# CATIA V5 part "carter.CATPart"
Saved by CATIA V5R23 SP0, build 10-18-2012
Part number: carter
Definition: carter
Source: made
Bounding box of the stored display mesh (mm): x -112 to 125, y -159 to 104, z -70 to 70
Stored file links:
  C:\wamp\www\COURS\CONCEPTION GMP1\TITRE 01-CATIA VOLUMIQUE\05--ACTIONNEUR DE VANNE\prof\CORRECTION\Assemblage\carter.CATPart
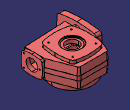
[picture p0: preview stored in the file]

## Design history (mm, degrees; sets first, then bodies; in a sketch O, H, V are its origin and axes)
Body1 "NONE" (main body)
  Solid1 "Manifold Solid #7438": solid without history
  Sketch1 "Esquisse.1" on face of Solid1, origin (125, 0, 0), H (0, 1, 0), V (0, 0, 1)
    projected arc E1 centre (-27.6401, 29.844) radius 10 from (-17.7954, 31.5995) to (-25.4425, 39.5995) ccw from edge [face of Solid1 | face of Solid1]
    projected arc E2 centre (-65, -136) radius 180 from (-25.4425, 39.5995) to (-65, 44) ccw from edge [face of Solid1 | face of Solid1]
    projected arc E3 centre (-65, -136) radius 180 from (-65, 44) to (-104.5575, 39.5995) ccw from edge [face of Solid1 | face of Solid1]
    projected arc E4 centre (-102.3599, 29.844) radius 10 from (-104.5575, 39.5995) to (-112.2046, 31.5995) ccw from edge [face of Solid1 | face of Solid1]
    projected arc E5 centre (65, 0) radius 180 from (-112.2046, 31.5995) to (-112.2046, -31.5995) ccw from edge [face of Solid1 | face of Solid1]
    projected arc E6 centre (-102.3599, -29.844) radius 10 from (-112.2046, -31.5995) to (-104.5575, -39.5995) ccw from edge [face of Solid1 | face of Solid1]
    projected arc E7 centre (-65, 136) radius 180 from (-104.5575, -39.5995) to (-65, -44) ccw from edge [face of Solid1 | face of Solid1]
    projected arc E8 centre (-65, 136) radius 180 from (-65, -44) to (-25.4425, -39.5995) ccw from edge [face of Solid1 | face of Solid1]
    projected arc E9 centre (-27.6401, -29.844) radius 10 from (-25.4425, -39.5995) to (-17.7954, -31.5995) ccw from edge [face of Solid1 | face of Solid1]
    projected arc E10 centre (-195, 0) radius 180 from (-17.7954, -31.5995) to (-17.7954, 31.5995) ccw from edge [face of Solid1 | face of Solid1]
    projected arc E11 centre (-65, 0) radius 27 from (-65, -27) to (-65, 27) ccw from edge [face of Solid1 | face of Solid1]
    projected arc E12 centre (-65, 0) radius 27 from (-65, 27) to (-65, -27) ccw from edge [face of Solid1 | face of Solid1]
  Pad1: profile Sketch1, direction (-1, 0, 0), up to face of Solid1
  Sketch2 "Esquisse.2" on face of Solid1, origin (125, -31.0159, 28.1579), H (0, 1, 0), V (0, 0, 1)
    point P1 (3.3758, -28.1579)
    reference projected point E1 (-33.9841, 15.8421) from vertex [face of Solid1 | face of Solid1 | face of Pad1]
    distance V P1 = 3.3758
    distance E1 P1 V = 44
  Hole1: placed by Sketch2, at (125, -27.6401, 0) direction (-1, 0, 0), diameter 6.647, up to face of Solid1, threaded "M8", thread diameter 8, thread depth 19.9, pitch 1.25
  Sketch3 "Esquisse.3" on face of Solid1, origin (-112, 0, 0), H (0, -1, 0), V (0, 0, 1)
    projected arc E1 centre (-15, 50) radius 6 from (-15, 44) to (-15, 56) ccw from edge [face of Solid1 | face of Solid1]
    projected arc E2 centre (-15, 50) radius 6 from (-15, 56) to (-15, 44) ccw from edge [face of Solid1 | face of Solid1]
    projected arc E3 centre (-15, -50) radius 6 from (-15, -56) to (-15, -44) ccw from edge [face of Solid1 | face of Solid1]
    projected arc E4 centre (-15, -50) radius 6 from (-15, -44) to (-15, -56) ccw from edge [face of Solid1 | face of Solid1]
    projected arc E5 centre (145, 50) radius 6 from (145, 56) to (145, 44) ccw from edge [face of Solid1 | face of Solid1]
    projected arc E6 centre (145, 50) radius 6 from (145, 44) to (145, 56) ccw from edge [face of Solid1 | face of Solid1]
    projected arc E7 centre (145, -50) radius 6 from (145, -56) to (145, -44) ccw from edge [face of Solid1 | face of Solid1]
    projected arc E8 centre (145, -50) radius 6 from (145, -44) to (145, -56) ccw from edge [face of Solid1 | face of Solid1]
  Pad2: profile Sketch3, direction (1, 0, 0), length 25
  Sketch4 "Esquisse.4" on face of Solid1, origin (125, 0, 0), H (0, 1, 0), V (0, 0, 1)
    point P1 (-102.3599, 29.844)
    point P2 (-102.3599, -29.844)
    reference projected arc E1 centre (-102.3599, 29.844) radius 10 from (-104.5575, 39.5995) to (-112.2046, 31.5995) ccw from edge [face of Pad1 | face of Solid1]
    reference projected arc E2 centre (-102.3599, -29.844) radius 10 from (-112.2046, -31.5995) to (-104.5575, -39.5995) ccw from edge [face of Solid1 | face of Solid1]
    concentricity: P1 E1, P2 E2
  UserPattern1: of Hole1, copies 3, at the points of Sketch4
  Sketch5 "Esquisse.5" on face of Solid1, origin (-112, 3.4837, -32.3675), H (0, 1, 0), V (0, 0, -1)
    point P1 (11.5163, 17.6325)
    reference projected arc E1 centre (11.5163, 17.6325) radius 12.5 from (23.9938, 18.3818) to (13.8396, 29.9147) ccw from edge [face of Solid1 | face of Solid1]
    concentricity: P1 E1
  Hole2: placed by Sketch5, at (-112, 15, -50) direction (1, 0, 0), diameter 10.106, depth 20, V-bottom angle 120, threaded "M12", thread diameter 12, thread depth 15, pitch 1.75
  Sketch6 "Esquisse.6" on face of Pad2, origin (-112, 0, 0), H (0, -1, 0), V (0, 0, 1)
    point P1 (-15, 50)
    point P2 (145, -50)
    point P3 (145, 50)
    reference projected arc E1 centre (-15, 50) radius 12.5 from (-17.3233, 62.2822) to (-27.4775, 50.7493) ccw from edge [face of Solid1 | face of Solid1]
    reference projected arc E2 centre (145, 50) radius 12.5 from (157.4775, 50.7493) to (147.3233, 62.2822) ccw from edge [face of Solid1 | face of Solid1]
    reference projected arc E3 centre (145, -50) radius 12.5 from (147.3233, -62.2822) to (157.4775, -50.7493) ccw from edge [face of Solid1 | face of Solid1]
    concentricity: P1 E1, P3 E2, P2 E3
  UserPattern2: of Hole2, copies 4, at the points of Sketch6
  Sketch7 "Esquisse.6" on face of Solid1, origin (0, 0, -66), H (1, 0, 0), V (0, -1, 0)
    projected arc E1 centre (-72.7461, -42) radius 4.25 from (-76.9961, -42) to (-68.4961, -42) ccw from edge [face of Solid1 | face of Solid1]
    projected arc E2 centre (-72.7461, -42) radius 4.25 from (-68.4961, -42) to (-76.9961, -42) ccw from edge [face of Solid1 | face of Solid1]
    projected arc E3 centre (-42, -72.7461) radius 4.25 from (-46.25, -72.7461) to (-37.75, -72.7461) ccw from edge [face of Solid1 | face of Solid1]
    projected arc E4 centre (-42, -72.7461) radius 4.25 from (-37.75, -72.7461) to (-46.25, -72.7461) ccw from edge [face of Solid1 | face of Solid1]
    projected arc E5 centre (0, -84) radius 4.25 from (-4.25, -84) to (4.25, -84) ccw from edge [face of Solid1 | face of Solid1]
    projected arc E6 centre (0, -84) radius 4.25 from (4.25, -84) to (-4.25, -84) ccw from edge [face of Solid1 | face of Solid1]
    projected arc E7 centre (42, -72.7461) radius 4.25 from (37.75, -72.7461) to (46.25, -72.7461) ccw from edge [face of Solid1 | face of Solid1]
    projected arc E8 centre (42, -72.7461) radius 4.25 from (46.25, -72.7461) to (37.75, -72.7461) ccw from edge [face of Solid1 | face of Solid1]
    projected arc E9 centre (72.7461, -42) radius 4.25 from (68.4961, -42) to (76.9961, -42) ccw from edge [face of Solid1 | face of Solid1]
    projected arc E10 centre (72.7461, -42) radius 4.25 from (76.9961, -42) to (68.4961, -42) ccw from edge [face of Solid1 | face of Solid1]
    projected arc E11 centre (84, 0) radius 4.25 from (79.75, 0) to (88.25, 0) ccw from edge [face of Solid1 | face of Solid1]
    projected arc E12 centre (84, 0) radius 4.25 from (88.25, 0) to (79.75, 0) ccw from edge [face of Solid1 | face of Solid1]
    projected arc E13 centre (72.7461, 42) radius 4.25 from (68.4961, 42) to (76.9961, 42) ccw from edge [face of Solid1 | face of Solid1]
    projected arc E14 centre (72.7461, 42) radius 4.25 from (76.9961, 42) to (68.4961, 42) ccw from edge [face of Solid1 | face of Solid1]
    projected arc E15 centre (42, 72.7461) radius 4.25 from (37.75, 72.7461) to (46.25, 72.7461) ccw from edge [face of Solid1 | face of Solid1]
    projected arc E16 centre (42, 72.7461) radius 4.25 from (46.25, 72.7461) to (37.75, 72.7461) ccw from edge [face of Solid1 | face of Solid1]
    projected arc E17 centre (0, 84) radius 4.25 from (-4.25, 84) to (4.25, 84) ccw from edge [face of Solid1 | face of Solid1]
    projected arc E18 centre (0, 84) radius 4.25 from (4.25, 84) to (-4.25, 84) ccw from edge [face of Solid1 | face of Solid1]
    projected arc E19 centre (-42, 72.7461) radius 4.25 from (-46.25, 72.7461) to (-37.75, 72.7461) ccw from edge [face of Solid1 | face of Solid1]
    projected arc E20 centre (-42, 72.7461) radius 4.25 from (-37.75, 72.7461) to (-46.25, 72.7461) ccw from edge [face of Solid1 | face of Solid1]
    projected arc E21 centre (-72.7461, 42) radius 4.25 from (-76.9961, 42) to (-68.4961, 42) ccw from edge [face of Solid1 | face of Solid1]
    projected arc E22 centre (-72.7461, 42) radius 4.25 from (-68.4961, 42) to (-76.9961, 42) ccw from edge [face of Solid1 | face of Solid1]
    projected arc E23 centre (-84, 0) radius 4.25 from (-88.25, 0) to (-79.75, 0) ccw from edge [face of Solid1 | face of Solid1]
    projected arc E24 centre (-84, 0) radius 4.25 from (-79.75, 0) to (-88.25, 0) ccw from edge [face of Solid1 | face of Solid1]
  Pad3: profile Sketch7, direction (0, 0, 1), length 16
  Sketch8 "Esquisse.7" on face of Pad3, origin (5.6035, -85.4634, -66), H (1, 0, 0), V (0, -1, 0)
    point P1 (-5.6035, -1.4634)
    reference projected point E1 (-5.6035, -85.4634) from axis of face of Solid1
    reference intersected line E2 through (-5.6035, 0) direction (0, 1) from yz-plane
    distance E1 P1 = 84
    coincidence: E2 P1
  Hole3: placed by Sketch8, at (0, -84, -66) direction (0, 0, 1), diameter 8.376, depth 16, threaded "M10", thread diameter 10, thread depth 16, pitch 1.5
  CircPattern1: of Hole3, instances 12, angular step 30, axis from face of Solid1
  Sketch9 on face of Solid1, origin (-16.7302, 56.6943, 59), H (1, 0, 0), V (0, 1, 0)
    point P1 (-37.2633, 0.9912)
    construction line L1 (16.7302, 54.8224) -> (16.7302, -174.3576)
    reference projected line E1 (-95.2698, -39.371) -> (-95.2698, -121.6943) from edge [face of Solid1 | face of Solid1]
    axis line L2 (-133.0786, -56.6943) -> (178.5032, -56.6943)
    reference projected arc E3 centre (16.7302, -226.6943) radius 254 from (75.3385, 20.4515) to (-41.878, 20.4515) ccw from edge [face of Solid1 | face of Solid1]
    distance L1 E1 = 112
    distance E3 L2 = 84
    distance P1 L1 = 53.9935
    distance P1 L2 = 57.6855
    vertical: L1 V
    horizontal: L2 H
  Hole4: placed by Sketch9, at (-53.9935, 57.6855, 59) direction (0, 0, -1), diameter 6.647, depth 20, V-bottom angle 120, threaded "M8", thread diameter 8, thread depth 18, pitch 1.25
  RectPattern1: of Hole4, direction 1 instances 2, spacing 115.371, along Y axis reversed, direction 2 instances 2, spacing 107.987, along X axis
